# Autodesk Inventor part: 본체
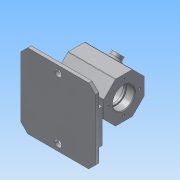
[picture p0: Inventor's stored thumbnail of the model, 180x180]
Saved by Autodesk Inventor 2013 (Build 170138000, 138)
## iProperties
Created: 2018-06
Part Number: 본체
Material: 알루미늄 6061
Document SubType Name: Modeling
Designer: Administrator
Density: 2.71 g/cm^3
Mass: 554.04 g
Surface Area: 601.93 cm^2
Volume: 204.443 cm^3
Author: Administrator
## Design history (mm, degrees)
sketch "스케치1"
  geometry: L1 (-30, -12.426)-(-30, 12.426); L2 (-30, 12.426)-(-12.426, 30); L3 (-12.426, 30)-(12.426, 30); L4 (12.426, 30)-(30, 12.426); L5 (30, 12.426)-(30, -12.426); L6 (30, -12.426)-(12.426, -30); L7 (12.426, -30)-(-12.426, -30); L8 (-12.426, -30)-(-30, -12.426); 3 further points
  constraints: 16 end point, 1 coincident, 1 midpoint, 1 vertical alignment, 17 other
  dimensions: "d0" = 30 distance from line of L5 point (0, 0)
extrude "돌출1" new body sketch "스케치1" stored distance "d1" = 70; taper "d2" = 0 deg
node "작업 평면1"
sketch "스케치2"
  geometry: L1 (-55, 55)-(55, 55); L2 (55, 55)-(55, -55); L3 (55, -55)-(-55, -55); L4 (-55, -55)-(-55, 55); L5 (-55, 55)-(55, -55); L6 (55, 55)-(-55, -55); 1 further point
  constraints: 12 end point, 2 midpoint, 2 parallel, 1 horizontal, 1 perpendicular
  dimensions: "d4" = 110 distance of L2.end L3.end; "d6" = 110 distance of L3.end L1.start
extrude "돌출2" join sketch "스케치2" distance "d7" = 5; taper "d8" = 0 deg
sketch "스케치3"
  geometry: L1 (55, 55)-(-55, 55) reference; L2 (-55, 55)-(-55, -55) reference; L3 (55, -25)-(-55, -25); L4 (-55, -25)-(-55, 25); L5 (-55, 25)-(55, 25); L6 (55, 25)-(55, -25); L7 (55, -25)-(-55, 25); L8 (-55, -25)-(55, 25); 1 further point
  constraints: 12 end point, 2 midpoint, 2 parallel, 1 horizontal, 1 perpendicular, 1 point on line
  dimensions: "d9" = 30 distance between parallel lines of L1 L5
extrude "돌출3" join sketch "스케치3" distance "d10" = 5; taper "d11" = 0 deg
chamfer "모따기1" distance "d12" = 10; stored, may be unused: second distance "d13" = 2, angle "d14" = 45 deg
sketch "스케치4"
  geometry: L1 (45, 55)-(-45, 55) reference; L2 (-55, 45)-(-55, 25) reference; C1 r 5 at (0, 45); 1 further point
  constraints: 1 centre point
  dimensions: "d15" = 10 diameter of C1; "d17" = 55 distance from line of C1.centre L2; "d18" = 10 distance from line of C1.centre L1
extrude "돌출4" cut sketch "스케치4" distance "d19" = 55 (= d17); taper "d20" = 0 deg
sketch "스케치5"
  geometry: L1 (55, 25)-(-55, 25) reference; L2 (-19, 5)-(19, 5); L3 (19, -5)-(-19, -5); A1 r 5 centre (19, 0) between (19, -5) and (19, 5); A2 r 5 centre (-19, 0) between (-19, 5) and (-19, -5); 2 further points
  constraints: 4 end point, 4 point on circle, 4 tangent, 2 centre point, 2 parallel, 1 horizontal alignment, 1 midpoint, 1 vertical alignment
  dimensions: "d21" = 38 distance of L2.start L2.end; "d23" = 5 radius of A1
extrude "돌출5" join sketch "스케치5" stored distance "d24" = 55 (= d17); taper "d25" = 0 deg
node "작업 평면2"
sketch "스케치6"
  geometry: C1 r 8 at (35, 12.426); 1 further point
  constraints: 1 centre point, 1 coincident
  dimensions: "d27" = 16 diameter of C1
extrude "돌출6" join sketch "스케치6" stored distance "d29" = 55 (= d17); taper "d30" = 0 deg
sketch "스케치7"
  geometry: 3 further points
  constraints: 1 coincident, 1 vertical alignment
  dimensions: "d31" = 23 distance of point (0, 0) point (0, 23)
hole "구멍1" sketch "스케치7" diameter "d32" = 28; stored, may be unused: countersink angle "d36" = 90 deg, drill point angle "d38" = 0 deg; dims "d33" = 6, "d34" = 32, "d35" = 12, "d37" = 15
hole "구멍2" sketch "스케치7" diameter "d39" = 3.242; stored, may be unused: countersink angle "d43" = 90 deg, drill point angle "d45" = 118 deg; dims "d40" = 8, "d41" = 32, "d42" = 12, "d44" = 10
hole "구멍3" diameter "d51" = 50; stored, may be unused: countersink angle "d55" = 90 deg, drill point angle "d57" = 0 deg; dims "d49" = 10, "d50" = 10, "d52" = 8, "d53" = 32, "d54" = 12, "d56" = 40
hole "구멍4" diameter "d60" = 8; stored, may be unused: countersink angle "d64" = 90 deg, drill point angle "d66" = 0 deg; dims "d58" = 10, "d59" = 10, "d61" = 8, "d62" = 32, "d63" = 12, "d65" = 40
sketch "스케치8"
  geometry: L1 (0, 0)-(0, 24.853) reference; L2 (70, 42.426)-(0, 42.426) reference; L3 (0, 24.853)-(0, 42.426) reference; 2 further points
  constraints: 1 other
  dimensions: "d67" = 30 distance from line of point (35, 12.426) L2; "d68" = 35 distance from line of point (35, 12.426) L1
feature "엠보싱1" sketch "스케치8" dims "d0" = 30, "d69" = 0.5, "d70" = 0
fillet "모깎기1" dims "d71" = 1, "d72" = 0.3, "d73" = 3, "d74" = 2
chamfer "모따기2" distance "d75" = 1; stored, may be unused: second distance "d76" = 2, angle "d77" = 45 deg
node "솔리드1"
mirror "대칭1"
pattern_circular "원형 패턴1" dims angle "d47" = 360 deg
mirror "대칭2"
other parameters: "d3" = -62, "d26" = 7
